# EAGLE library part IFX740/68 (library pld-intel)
PLD
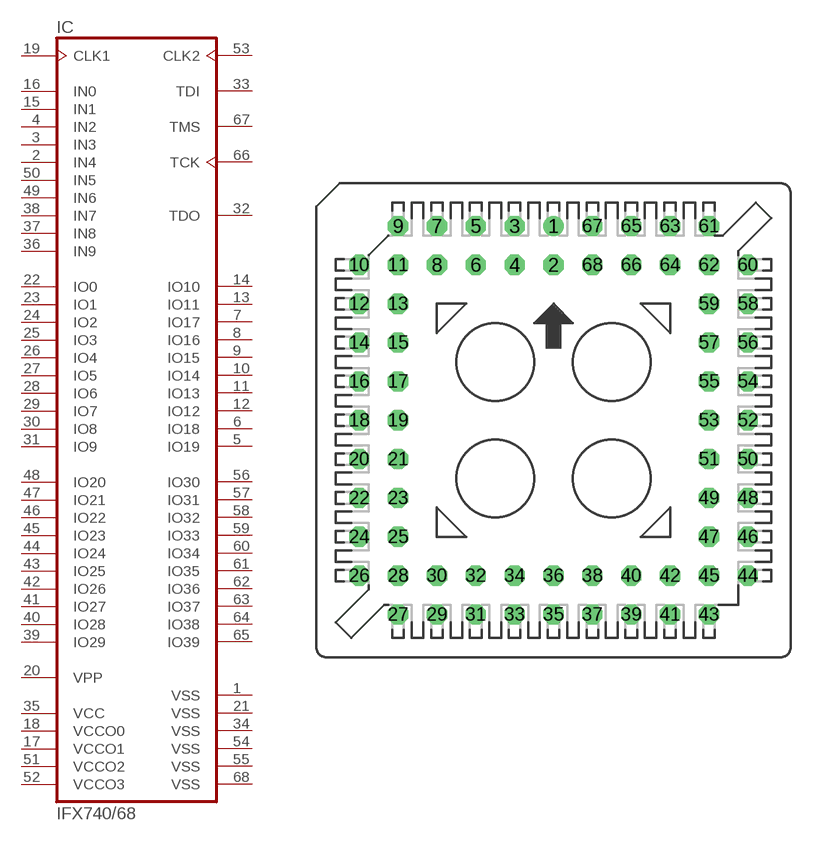
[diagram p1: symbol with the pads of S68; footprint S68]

Designator prefix IC

## IFX740/68 (OC_FARNELL: unknown; OC_NEWARK: unknown)  [S68]
1  VSS  pwr
2  IN4  in
3  IN3  in
4  IN2  in
5  IO19
6  IO18
7  IO17
8  IO16
9  IO15
10  IO14
11  IO13
12  IO12
13  IO11
14  IO10
15  IN1  in
16  IN0  in
17  VCCO1  sup
18  VCCO0  sup
19  CLK1  in
20  VPP  sup
21  VSS  pwr
22  IO0
23  IO1
24  IO2
25  IO3
26  IO4
27  IO5
28  IO6
29  IO7
30  IO8
31  IO9
32  TDO  out
33  TDI  in
34  VSS  pwr
35  VCC  pwr
36  IN9  in
37  IN8  in
38  IN7  in
39  IO29
40  IO28
41  IO27
42  IO26
43  IO25
44  IO24
45  IO23
46  IO22
47  IO21
48  IO20
49  IN6  in
50  IN5  in
51  VCCO2  sup
52  VCCO3  sup
53  CLK2  in
54  VSS  pwr
55  VSS  pwr
56  IO30
57  IO31
58  IO32
59  IO33
60  IO34
61  IO35
62  IO36
63  IO37
64  IO38
65  IO39
66  TCK  in
67  TMS  in
68  VSS  pwr

## Footprint S68 (pad centres in mm)
PLCC SOCKET
drill 0.813 round: 1 0,12.7
drill 0.813 octagon: 2 0,10.16; 3 -2.54,12.7; 4 -2.54,10.16; 5 -5.08,12.7; 6 -5.08,10.16; 7 -7.62,12.7; 8 -7.62,10.16; 9 -10.16,12.7; 10 -12.7,10.16; 11 -10.16,10.16; 12 -12.7,7.62; 13 -10.16,7.62; 14 -12.7,5.08; 15 -10.16,5.08; 16 -12.7,2.54; 17 -10.16,2.54; 18 -12.7,0; 19 -10.16,0; 20 -12.7,-2.54; 21 -10.16,-2.54; 22 -12.7,-5.08; 23 -10.16,-5.08; 24 -12.7,-7.62; 25 -10.16,-7.62; 26 -12.7,-10.16; 27 -10.16,-12.7; 28 -10.16,-10.16; 29 -7.62,-12.7; 30 -7.62,-10.16; 31 -5.08,-12.7; 32 -5.08,-10.16; 33 -2.54,-12.7; 34 -2.54,-10.16; 35 0,-12.7; 36 0,-10.16; 37 2.54,-12.7; 38 2.54,-10.16; 39 5.08,-12.7; 40 5.08,-10.16; 41 7.62,-12.7; 42 7.62,-10.16; 43 10.16,-12.7; 44 12.7,-10.16; 45 10.16,-10.16; 46 12.7,-7.62; 47 10.16,-7.62; 48 12.7,-5.08; 49 10.16,-5.08; 50 12.7,-2.54; 51 10.16,-2.54; 52 12.7,0; 53 10.16,0; 54 12.7,2.54; 55 10.16,2.54; 56 12.7,5.08; 57 10.16,5.08; 58 12.7,7.62; 59 10.16,7.62; 60 12.7,10.16; 61 10.16,12.7; 62 10.16,10.16; 63 7.62,12.7; 64 7.62,10.16; 65 5.08,12.7; 66 5.08,10.16; 67 2.54,12.7; 68 2.54,10.16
